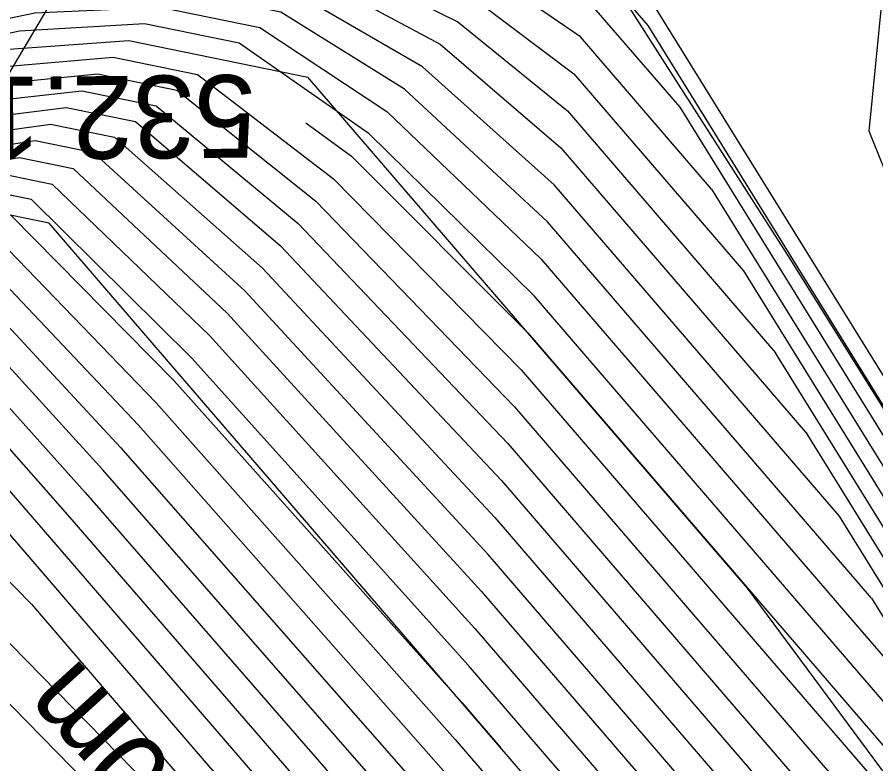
# Model space of a CAD drawing. Extents: x -866683 to -866410, y -1041951 to -1040252.
# Drawn here: x -866456.13 to -866453.011, y -1041913.962 to -1041911.251 of the extents above; entities that cross this region are included whole.
import ezdxf

# ---------------------------------------------------------------- set-up
doc = ezdxf.new("R2010")
doc.units = 0
for name, color, linetype in [('BREAKLINE', 7, 'Continuous'), ('V-HL', 7, 'Continuous'), ('V-VEDL', 7, 'Continuous'), ('V_po_cm', 7, 'Continuous')]:
    doc.layers.add(name, color=color, linetype=linetype)

msp = doc.modelspace()

# ---------------------------------------------------------------- linework, layer by layer
at = {"layer": 'BREAKLINE'}
msp.add_lwpolyline([(-866451.679, -1041950.508), (-866455.618, -1041922.473), (-866456.719, -1041912.396), (-866455.207, -1041909.853), (-866453.752, -1041908.342), (-866450, -1041907.538), (-866447.7, -1041908.076), (-866445.165, -1041909.459), (-866437.422, -1041915.176), (-866426.565, -1041925.108), (-866438.22, -1041915.868), (-866445.312, -1041910.554), (-866447.7, -1041908.076)], dxfattribs=at)
at = {"layer": 'V-HL'}
msp.add_lwpolyline([(-866454.1336, -1041910.9392), (-866453.9375, -1041911.167), (-866453.3211, -1041912.1323), (-866452.4979, -1041913.4504)], dxfattribs=at)
at = {"layer": 'V-VEDL'}
for points in [[(-866464.1795, -1041906.7476), (-866460.1736, -1041910.2204), (-866458.6026, -1041911.3017), (-866457.4635, -1041911.7277), (-866456.7563, -1041911.4985), (-866456.1765, -1041911.3679), (-866455.724, -1041911.3359), (-866455.0738, -1041911.4689)], [(-866456.0139, -1041911.9987), (-866456.2926, -1041911.9417), (-866456.7284, -1041912.0338), (-866457.4606, -1041912.2465), (-866458.4892, -1041912.5798), (-866459.6567, -1041912.3845), (-866460.9629, -1041911.6604), (-866463.8529, -1041909.155)], [(-866437.9513, -1041933.9895), (-866436.2679, -1041931.188), (-866435.7213, -1041930.1825), (-866435.4698, -1041929.5721), (-866435.5134, -1041929.3569), (-866435.5157, -1041928.9796), (-866435.4765, -1041928.44), (-866435.3961, -1041927.7383), (-866436.6575, -1041926.4083), (-866439.2609, -1041924.4499), (-866443.2062, -1041921.8632), (-866446.067, -1041920.1994), (-866447.8432, -1041919.4586), (-866448.5349, -1041919.6407), (-866449.3795, -1041919.1431), (-866450.3771, -1041917.9657), (-866451.5277, -1041916.1086), (-866452.5609, -1041914.5613), (-866453.4767, -1041913.3239), (-866455.0738, -1041911.4689)], [(-866453.6171, -1041916.4043), (-866455.6514, -1041914.0403), (-866456.43, -1041913.2461), (-866456.9701, -1041912.8398), (-866457.2717, -1041912.8213), (-866457.8386, -1041912.9275), (-866458.6706, -1041913.1584), (-866459.7678, -1041913.5139), (-866460.795, -1041913.4946), (-866461.7521, -1041913.1004), (-866463.5263, -1041911.5623)], [(-866439.4444, -1041935.2819), (-866437.4367, -1041931.9407), (-866436.7848, -1041930.7414), (-866436.4848, -1041930.0134), (-866436.5368, -1041929.7567), (-866436.5395, -1041929.3067), (-866436.4928, -1041928.6632), (-866436.3968, -1041927.8263), (-866437.5569, -1041926.4658), (-866439.973, -1041924.5818), (-866443.6451, -1041922.1742), (-866446.3437, -1041920.6351), (-866448.069, -1041919.9646), (-866448.8208, -1041920.1625), (-866449.538, -1041919.9458), (-866450.2207, -1041919.3143), (-866450.8689, -1041918.2681), (-866451.8006, -1041916.9903), (-866453.016, -1041915.4809), (-866456.0139, -1041911.9987)]]:
    msp.add_lwpolyline(points, dxfattribs=at)
at = {"layer": 'V_po_cm'}
for points in [[(-866461.9684, -1041906.7527), (-866459.4633, -1041908.9245), (-866457.654, -1041910.3271), (-866456.5404, -1041910.9608), (-866456.1225, -1041910.8254), (-866455.6798, -1041910.7687), (-866455.2123, -1041910.7907), (-866454.72, -1041910.8914), (-866454.3357, -1041911.0237), (-866454.0595, -1041911.1874), (-866453.7233, -1041911.5779)], [(-866453.0266, -1041913.3603), (-866454.2033, -1041911.9934), (-866454.7225, -1041911.5118), (-866455.1726, -1041911.2321), (-866455.5534, -1041911.1541), (-866456.0109, -1041911.1682), (-866456.5451, -1041911.2741), (-866457.1558, -1041911.4721), (-866458.2864, -1041910.9768), (-866459.9369, -1041909.7884), (-866462.1072, -1041907.9069), (-866463.5789, -1041906.9024)], [(-866453.6072, -1041911.875), (-866454.0835, -1041911.3217), (-866454.4002, -1041911.105), (-866454.7954, -1041910.9482), (-866455.2691, -1041910.8513), (-866455.735, -1041910.8352), (-866456.1929, -1041910.9002), (-866456.643, -1041911.046), (-866457.7594, -1041910.4354), (-866459.5423, -1041909.0685), (-866461.9915, -1041906.9451)], [(-866463.5642, -1041907.1206), (-866462.1303, -1041908.0993), (-866460.0158, -1041909.9324), (-866458.3918, -1041911.0851), (-866457.2584, -1041911.5573), (-866456.6155, -1041911.3489), (-866456.0661, -1041911.2347), (-866455.6103, -1041911.2147), (-866455.248, -1041911.2888), (-866454.787, -1041911.5932), (-866454.2273, -1041912.1278), (-866452.9104, -1041913.6573)], [(-866462.0146, -1041907.1374), (-866459.6212, -1041909.2125), (-866457.8648, -1041910.5437), (-866456.7455, -1041911.1312), (-866456.2634, -1041910.9749), (-866455.7902, -1041910.9018), (-866455.326, -1041910.9118), (-866454.8708, -1041911.005), (-866454.4647, -1041911.1864), (-866454.1075, -1041911.4561), (-866453.4911, -1041912.172)], [(-866452.7943, -1041913.9544), (-866454.2513, -1041912.2621), (-866454.8515, -1041911.6746), (-866455.3234, -1041911.3456), (-866455.6671, -1041911.2753), (-866456.1213, -1041911.3013), (-866456.6859, -1041911.4237), (-866457.361, -1041911.6425), (-866458.4972, -1041911.1934), (-866460.0947, -1041910.0764), (-866462.1534, -1041908.2917), (-866463.5495, -1041907.3388)], [(-866462.0378, -1041907.3298), (-866459.7001, -1041909.3565), (-866457.9702, -1041910.652), (-866456.8481, -1041911.2164), (-866456.3338, -1041911.0497), (-866455.8454, -1041910.9684), (-866455.3829, -1041910.9724), (-866454.9463, -1041911.0617), (-866454.5291, -1041911.2677), (-866454.1314, -1041911.5904), (-866453.3749, -1041912.4691)], [(-866462.0609, -1041907.5222), (-866459.779, -1041909.5005), (-866458.0756, -1041910.7603), (-866456.9507, -1041911.3016), (-866456.4042, -1041911.1245), (-866455.9006, -1041911.035), (-866455.4397, -1041911.033), (-866455.0217, -1041911.1185), (-866454.5936, -1041911.3491), (-866454.1554, -1041911.7247), (-866453.2588, -1041912.7662)], [(-866464.0149, -1041919.5667), (-866464.1225, -1041917.511), (-866464.2372, -1041915.5405), (-866464.3589, -1041913.6552), (-866464.4877, -1041911.8549), (-866464.5437, -1041910.5382), (-866464.5268, -1041909.705), (-866464.4371, -1041909.3554), (-866464.355, -1041908.8981), (-866464.2806, -1041908.3332), (-866464.2137, -1041907.6608), (-866463.5201, -1041907.7752), (-866462.1997, -1041908.6764), (-866460.2526, -1041910.3644), (-866458.708, -1041911.41), (-866457.5661, -1041911.8129), (-866456.8268, -1041911.5733), (-866456.2317, -1041911.4345), (-866455.7809, -1041911.3965), (-866455.4743, -1041911.4592), (-866454.9804, -1041911.8373), (-866454.2992, -1041912.5308), (-866452.5621, -1041914.5485)], [(-866453.1427, -1041913.0632), (-866454.1794, -1041911.8591), (-866454.6581, -1041911.4305), (-866455.0971, -1041911.1753), (-866455.4966, -1041911.0936), (-866455.9557, -1041911.1016), (-866456.4746, -1041911.1993), (-866457.0533, -1041911.3868), (-866458.181, -1041910.8685), (-866459.8579, -1041909.6444), (-866462.084, -1041907.7146)], [(-866463.994, -1041919.6179), (-866464.1029, -1041917.5376), (-866464.2169, -1041915.5731), (-866464.3358, -1041913.7246), (-866464.4598, -1041911.992), (-866464.5119, -1041910.718), (-866464.4922, -1041909.9025), (-866464.4006, -1041909.5456), (-866464.3179, -1041909.0899), (-866464.2441, -1041908.5354), (-866464.1791, -1041907.8823), (-866463.5054, -1041907.9934), (-866462.2228, -1041908.8688), (-866460.3315, -1041910.5084), (-866458.8134, -1041911.5182), (-866457.6687, -1041911.8981), (-866456.8972, -1041911.6481), (-866456.2869, -1041911.5011), (-866455.8377, -1041911.457), (-866455.5498, -1041911.516), (-866455.0449, -1041911.9186), (-866454.3232, -1041912.6651), (-866452.446, -1041914.8455)], [(-866463.9732, -1041919.6692), (-866464.0834, -1041917.5641), (-866464.1965, -1041915.6057), (-866464.3127, -1041913.794), (-866464.4318, -1041912.1292), (-866464.4801, -1041910.8978), (-866464.4575, -1041910.1), (-866464.364, -1041909.7358), (-866464.2807, -1041909.2817), (-866464.2076, -1041908.7376), (-866464.1445, -1041908.1037), (-866463.4907, -1041908.2115), (-866462.2459, -1041909.0611), (-866460.4104, -1041910.6524), (-866458.9188, -1041911.6265), (-866457.7712, -1041911.9833), (-866456.9676, -1041911.7229), (-866456.342, -1041911.5677), (-866455.8946, -1041911.5176), (-866455.6252, -1041911.5727), (-866455.1094, -1041912), (-866454.3471, -1041912.7994), (-866452.3298, -1041915.1426)], [(-866463.9523, -1041919.7205), (-866464.0638, -1041917.5906), (-866464.1762, -1041915.6382), (-866464.2896, -1041913.8635), (-866464.4038, -1041912.2663), (-866464.4483, -1041911.0776), (-866464.4228, -1041910.2975), (-866464.3275, -1041909.926), (-866464.2436, -1041909.4735), (-866464.1711, -1041908.9398), (-866464.11, -1041908.3252), (-866463.476, -1041908.4297), (-866462.2691, -1041909.2535), (-866460.4893, -1041910.7964), (-866459.0242, -1041911.7348), (-866457.8738, -1041912.0686), (-866457.038, -1041911.7977), (-866456.3972, -1041911.6343), (-866455.9514, -1041911.5782), (-866455.7006, -1041911.6295), (-866455.1738, -1041912.0814), (-866454.3711, -1041912.9338), (-866452.2137, -1041915.4397)], [(-866463.9314, -1041919.7718), (-866464.0442, -1041917.6171), (-866464.1559, -1041915.6708), (-866464.2665, -1041913.9329), (-866464.3759, -1041912.4034), (-866464.4164, -1041911.2574), (-866464.3881, -1041910.495), (-866464.291, -1041910.1162), (-866464.2065, -1041909.6652), (-866464.1346, -1041909.142), (-866464.0754, -1041908.5467), (-866463.4613, -1041908.6479), (-866462.2922, -1041909.4459), (-866460.5683, -1041910.9404), (-866459.1296, -1041911.8431), (-866457.9764, -1041912.1538), (-866457.1084, -1041911.8725), (-866456.4524, -1041911.7008), (-866456.0083, -1041911.6388), (-866455.7761, -1041911.6863), (-866455.2383, -1041912.1627), (-866454.3951, -1041913.0681), (-866452.0976, -1041915.7367)], [(-866451.9815, -1041916.0338), (-866454.4191, -1041913.2024), (-866455.3028, -1041912.2441), (-866455.8515, -1041911.7431), (-866456.0651, -1041911.6993), (-866456.5076, -1041911.7674), (-866457.1789, -1041911.9473), (-866458.0789, -1041912.239), (-866459.2351, -1041911.9514), (-866460.6472, -1041911.0844), (-866462.3153, -1041909.6382), (-866463.4466, -1041908.8661), (-866464.0408, -1041908.7681), (-866464.0981, -1041909.3442), (-866464.1693, -1041909.857), (-866464.2544, -1041910.3064), (-866464.3535, -1041910.6925), (-866464.3846, -1041911.4372), (-866464.3479, -1041912.5405), (-866464.2433, -1041914.0023), (-866464.1356, -1041915.7034), (-866464.0247, -1041917.6436), (-866463.9105, -1041919.8231)], [(-866463.8897, -1041919.8744), (-866464.0051, -1041917.6701), (-866464.1153, -1041915.7359), (-866464.2202, -1041914.0717), (-866464.32, -1041912.6776), (-866464.3528, -1041911.617), (-866464.3188, -1041910.89), (-866464.2179, -1041910.4967), (-866464.1322, -1041910.0488), (-866464.0616, -1041909.5464), (-866464.0062, -1041908.9896), (-866463.4319, -1041909.0843), (-866462.3385, -1041909.8306), (-866460.7261, -1041911.2284), (-866459.3405, -1041912.0596), (-866458.1815, -1041912.3242), (-866457.2493, -1041912.0221), (-866456.5628, -1041911.834), (-866456.122, -1041911.7599), (-866455.9269, -1041911.7998), (-866455.3673, -1041912.3255), (-866454.443, -1041913.3368), (-866451.8653, -1041916.3308)], [(-866463.8688, -1041919.9257), (-866463.9855, -1041917.6967), (-866464.0949, -1041915.7685), (-866464.1971, -1041914.1412), (-866464.292, -1041912.8147), (-866464.321, -1041911.7968), (-866464.2841, -1041911.0875), (-866464.1814, -1041910.6869), (-866464.095, -1041910.2406), (-866464.0251, -1041909.7486), (-866463.9717, -1041909.2111), (-866463.4172, -1041909.3025), (-866462.3616, -1041910.023), (-866460.805, -1041911.3724), (-866459.4459, -1041912.1679), (-866458.2841, -1041912.4094), (-866457.3197, -1041912.0969), (-866456.618, -1041911.9006), (-866456.1789, -1041911.8205), (-866456.0024, -1041911.8566), (-866455.4317, -1041912.4068), (-866454.467, -1041913.4711), (-866451.7492, -1041916.6279)], [(-866451.6331, -1041916.9249), (-866454.491, -1041913.6054), (-866455.4962, -1041912.4882), (-866456.0778, -1041911.9134), (-866456.2357, -1041911.8811), (-866456.6732, -1041911.9672), (-866457.3901, -1041912.1717), (-866458.3867, -1041912.4946), (-866459.5513, -1041912.2762), (-866460.884, -1041911.5164), (-866462.3847, -1041910.2153), (-866463.4024, -1041909.5207), (-866463.9371, -1041909.4325), (-866463.9886, -1041909.9508), (-866464.0579, -1041910.4324), (-866464.1448, -1041910.8771), (-866464.2495, -1041911.285), (-866464.2892, -1041911.9766), (-866464.264, -1041912.9518), (-866464.174, -1041914.2106), (-866464.0746, -1041915.8011), (-866463.9659, -1041917.7232), (-866463.8479, -1041919.9769)], [(-866448.1918, -1041919.0146), (-866449.1759, -1041918.2014), (-866450.5246, -1041916.4121), (-866452.238, -1041913.6466), (-866453.0351, -1041911.6643), (-866452.916, -1041910.4653), (-866451.8807, -1041910.0496), (-866451.1969, -1041909.7645), (-866450.8647, -1041909.6101), (-866450.8839, -1041909.5864), (-866450.889, -1041909.5577), (-866450.8798, -1041909.524), (-866450.8563, -1041909.4853), (-866450.853, -1041909.4547), (-866450.8698, -1041909.4323), (-866450.9438, -1041909.4039)], [(-866463.8062, -1041920.0795), (-866463.9268, -1041917.7762), (-866464.034, -1041915.8662), (-866464.1278, -1041914.3495), (-866464.2081, -1041913.226), (-866464.2256, -1041912.3362), (-866464.1801, -1041911.68), (-866464.0717, -1041911.2575), (-866463.9836, -1041910.8159), (-866463.9156, -1041910.3552), (-866463.8679, -1041909.8755), (-866463.373, -1041909.9571), (-866462.431, -1041910.6001), (-866461.0418, -1041911.8044), (-866459.7621, -1041912.4928), (-866458.5918, -1041912.665), (-866457.531, -1041912.3213), (-866456.7835, -1041912.1004), (-866456.3494, -1041912.0022), (-866456.2287, -1041912.0269), (-866455.6252, -1041912.6509), (-866454.5389, -1041913.8741), (-866451.4009, -1041917.519)], [(-866463.7853, -1041920.1308), (-866463.9072, -1041917.8027), (-866464.0137, -1041915.8988), (-866464.1046, -1041914.4189), (-866464.1802, -1041913.3631), (-866464.1938, -1041912.516), (-866464.1455, -1041911.8775), (-866464.0352, -1041911.4477), (-866463.9464, -1041911.0077), (-866463.8791, -1041910.5574), (-866463.8334, -1041910.0969), (-866463.3583, -1041910.1753), (-866462.4541, -1041910.7924), (-866461.1207, -1041911.9484), (-866459.8675, -1041912.601), (-866458.6944, -1041912.7503), (-866457.6014, -1041912.3961), (-866456.8387, -1041912.1669), (-866456.4063, -1041912.0628), (-866456.3041, -1041912.0837), (-866455.6896, -1041912.7323), (-866454.5629, -1041914.0085), (-866451.2847, -1041917.8161)], [(-866463.7645, -1041920.1821), (-866463.8876, -1041917.8293), (-866463.9933, -1041915.9313), (-866464.0815, -1041914.4883), (-866464.1522, -1041913.5002), (-866464.162, -1041912.6958), (-866464.1108, -1041912.075), (-866463.9987, -1041911.638), (-866463.9093, -1041911.1995), (-866463.8427, -1041910.7596), (-866463.7988, -1041910.3184), (-866463.3436, -1041910.3934), (-866462.4773, -1041910.9848), (-866461.1996, -1041912.0924), (-866459.9729, -1041912.7093), (-866458.7969, -1041912.8355), (-866457.6718, -1041912.4709), (-866456.8939, -1041912.2335), (-866456.4631, -1041912.1234), (-866456.3795, -1041912.1405), (-866455.7541, -1041912.8136), (-866454.5868, -1041914.1428), (-866451.1686, -1041918.1132)], [(-866451.0525, -1041918.4102), (-866454.6108, -1041914.2771), (-866455.8186, -1041912.895), (-866456.455, -1041912.1973), (-866456.52, -1041912.184), (-866456.9491, -1041912.3001), (-866457.7423, -1041912.5457), (-866458.8995, -1041912.9207), (-866460.0783, -1041912.8176), (-866461.2786, -1041912.2364), (-866462.5004, -1041911.1772), (-866463.3289, -1041910.6116), (-866463.7642, -1041910.5399), (-866463.8062, -1041910.9618), (-866463.8721, -1041911.3913), (-866463.9621, -1041911.8282), (-866464.0761, -1041912.2725), (-866464.1302, -1041912.8756), (-866464.1243, -1041913.6373), (-866464.0584, -1041914.5578), (-866463.973, -1041915.9639), (-866463.8681, -1041917.8558), (-866463.7436, -1041920.2334)], [(-866455.5596, -1041910.706), (-866455.1554, -1041910.7301), (-866454.6445, -1041910.8346), (-866454.2712, -1041910.9423), (-866454.0356, -1041911.0531), (-866453.8394, -1041911.2809)], [(-866463.7227, -1041920.2847), (-866463.8485, -1041917.8823), (-866463.9527, -1041915.9965), (-866464.0353, -1041914.6272), (-866464.0963, -1041913.7744), (-866464.0983, -1041913.0554), (-866464.0414, -1041912.47), (-866463.9256, -1041912.0184), (-866463.835, -1041911.5831), (-866463.7697, -1041911.164), (-866463.7296, -1041910.7613), (-866463.3142, -1041910.8298), (-866462.5235, -1041911.3695), (-866461.3575, -1041912.3804), (-866460.1837, -1041912.9259), (-866459.0021, -1041913.0059), (-866457.8127, -1041912.6205), (-866457.0043, -1041912.3667), (-866456.5769, -1041912.2446), (-866456.5304, -1041912.2541), (-866455.883, -1041912.9764), (-866454.6348, -1041914.4115), (-866450.9364, -1041918.7073)], [(-866463.7019, -1041920.3359), (-866463.8289, -1041917.9088), (-866463.9324, -1041916.029), (-866464.0122, -1041914.6966), (-866464.0683, -1041913.9116), (-866464.0665, -1041913.2352), (-866464.0068, -1041912.6675), (-866463.889, -1041912.2086), (-866463.7978, -1041911.7748), (-866463.7332, -1041911.3662), (-866463.695, -1041910.9828), (-866463.2995, -1041911.048), (-866462.5467, -1041911.5619), (-866461.4364, -1041912.5244), (-866460.2891, -1041913.0342), (-866459.1046, -1041913.0911), (-866457.8831, -1041912.6953), (-866457.0595, -1041912.4333), (-866456.6337, -1041912.3051), (-866456.6058, -1041912.3108), (-866455.9475, -1041913.0577), (-866454.6587, -1041914.5458), (-866450.8202, -1041919.0043)], [(-866453.9556, -1041910.9838), (-866450.5491, -1041916.4822), (-866449.2051, -1041918.2601), (-866448.2204, -1041919.0667), (-866447.5949, -1041918.902), (-866445.7626, -1041919.7202), (-866442.7235, -1041921.5211), (-866438.4776, -1041924.3049), (-866435.6682, -1041926.3451), (-866434.2952, -1041927.6416), (-866434.3586, -1041928.1946), (-866434.3894, -1041928.6198), (-866434.3877, -1041928.9172), (-866434.3533, -1041929.0867), (-866434.5515, -1041929.5677), (-866434.9823, -1041930.3602), (-866436.3089, -1041932.5679)], [(-866463.681, -1041920.3872), (-866463.8094, -1041917.9353), (-866463.912, -1041916.0616), (-866463.989, -1041914.766), (-866464.0404, -1041914.0487), (-866464.0347, -1041913.415), (-866463.9721, -1041912.865), (-866463.8525, -1041912.3988), (-866463.7607, -1041911.9666), (-866463.6967, -1041911.5684), (-866463.6605, -1041911.2043), (-866463.2848, -1041911.2662), (-866462.5698, -1041911.7543), (-866461.5153, -1041912.6684), (-866460.3945, -1041913.1424), (-866459.2072, -1041913.1763), (-866457.9535, -1041912.7701), (-866457.1147, -1041912.4999), (-866456.6906, -1041912.3657), (-866456.6813, -1041912.3676), (-866456.012, -1041913.1391), (-866454.6827, -1041914.6801), (-866450.7041, -1041919.3014)], [(-866453.8394, -1041911.2809), (-866452.7335, -1041913.066)], [(-866453.7233, -1041911.5779), (-866450.5178, -1041916.7519), (-866449.2368, -1041918.4207), (-866448.2776, -1041919.1711), (-866447.64, -1041919.0032), (-866445.8179, -1041919.8073), (-866442.8113, -1041921.5833), (-866438.6201, -1041924.3313), (-866435.8481, -1041926.3566), (-866434.4954, -1041927.6592), (-866434.5619, -1041928.2392), (-866434.5942, -1041928.6852), (-866434.5924, -1041928.9971), (-866434.5563, -1041929.175), (-866434.7642, -1041929.6795), (-866435.216, -1041930.5107), (-866436.6075, -1041932.8263)], [(-866455.0814, -1041911.6348), (-866454.916, -1041911.7559), (-866454.2752, -1041912.3964), (-866452.6782, -1041914.2514)], [(-866453.6072, -1041911.875), (-866450.5022, -1041916.8868), (-866449.2527, -1041918.5009), (-866448.3062, -1041919.2233), (-866447.6626, -1041919.0538), (-866445.8456, -1041919.8509), (-866442.8552, -1041921.6144), (-866438.6913, -1041924.3444), (-866435.938, -1041926.3623), (-866434.5954, -1041927.668), (-866434.6635, -1041928.2615), (-866434.6966, -1041928.7179), (-866434.6947, -1041929.0371), (-866434.6578, -1041929.2191), (-866434.8706, -1041929.7354), (-866435.3329, -1041930.586), (-866436.7568, -1041932.9556)], [(-866457.6353, -1041912.3031), (-866457.4606, -1041912.2465), (-866456.7284, -1041912.0338), (-866456.2926, -1041911.9417), (-866456.1532, -1041911.9702), (-866455.5607, -1041912.5695), (-866454.5149, -1041913.7398), (-866454.3758, -1041913.9013)], [(-866453.4911, -1041912.172), (-866450.4866, -1041917.0217), (-866449.2685, -1041918.5812), (-866448.3348, -1041919.2755), (-866447.6852, -1041919.1044), (-866445.8733, -1041919.8945), (-866442.899, -1041921.6455), (-866438.7625, -1041924.3576), (-866436.028, -1041926.3681), (-866434.6955, -1041927.6768), (-866434.7651, -1041928.2839), (-866434.799, -1041928.7506), (-866434.797, -1041929.0771), (-866434.7593, -1041929.2632), (-866434.9769, -1041929.7913), (-866435.4498, -1041930.6612), (-866436.9061, -1041933.0848)], [(-866450.588, -1041919.5984), (-866454.2618, -1041915.3313), (-866455.5541, -1041913.8301), (-866456.3021, -1041912.9613), (-866456.5055, -1041912.7249), (-866456.6612, -1041912.566), (-866456.7692, -1041912.4848), (-866456.8295, -1041912.4811), (-866457.2815, -1041912.612), (-866458.1251, -1041912.8776), (-866459.3604, -1041913.2779), (-866460.5167, -1041913.2562)], [(-866437.0554, -1041933.2141), (-866435.5667, -1041930.7365), (-866435.0833, -1041929.8472), (-866434.8608, -1041929.3074), (-866434.8994, -1041929.1171), (-866434.9014, -1041928.7833), (-866434.8668, -1041928.3062), (-866434.7956, -1041927.6856), (-866436.1179, -1041926.3738), (-866438.8337, -1041924.3708), (-866442.9429, -1041921.6766), (-866445.901, -1041919.938), (-866447.7078, -1041919.155), (-866448.3633, -1041919.3276), (-866449.2844, -1041918.6615), (-866450.4709, -1041917.1565), (-866453.3749, -1041912.4691)], [(-866460.6559, -1041913.3754), (-866459.5641, -1041913.3959), (-866458.3978, -1041913.018), (-866457.56, -1041912.7697), (-866457.0506, -1041912.6512), (-866456.8697, -1041912.6623), (-866456.5456, -1041912.9061), (-866456.0784, -1041913.3826), (-866455.4682, -1041914.0918), (-866454.574, -1041915.1306), (-866453.3959, -1041916.4992), (-866450.4719, -1041919.8955)], [(-866437.2047, -1041933.3433), (-866435.6835, -1041930.8117), (-866435.1896, -1041929.9031), (-866434.9623, -1041929.3515), (-866435.0017, -1041929.157), (-866435.0037, -1041928.816), (-866434.9684, -1041928.3285), (-866434.8957, -1041927.6944), (-866436.2078, -1041926.3796), (-866438.9049, -1041924.384), (-866442.9868, -1041921.7077), (-866445.9286, -1041919.9816), (-866447.7303, -1041919.2056), (-866448.3919, -1041919.3798), (-866449.3002, -1041918.7417), (-866450.4553, -1041917.2914), (-866453.2588, -1041912.7662)], [(-866451.6641, -1041918.835), (-866452.6136, -1041917.7318), (-866453.8004, -1041916.3528), (-866455.2243, -1041914.698), (-866456.3144, -1041913.5861), (-866457.0706, -1041913.0173), (-866457.4928, -1041912.9914), (-866458.1171, -1041913.0852), (-866458.9433, -1041913.2987), (-866459.9715, -1041913.6319)], [(-866437.354, -1041933.4725), (-866435.8004, -1041930.887), (-866435.296, -1041929.959), (-866435.0638, -1041929.3956), (-866435.1041, -1041929.197), (-866435.1061, -1041928.8487), (-866435.07, -1041928.3508), (-866434.9958, -1041927.7032), (-866436.2978, -1041926.3853), (-866438.9761, -1041924.3972), (-866443.0307, -1041921.7388), (-866445.9563, -1041920.0252), (-866447.7529, -1041919.2562), (-866448.4205, -1041919.432), (-866449.3161, -1041918.822), (-866450.4397, -1041917.4262), (-866453.1427, -1041913.0632)], [(-866453.0266, -1041913.3603), (-866450.424, -1041917.5611), (-866449.332, -1041918.9023), (-866448.4491, -1041919.4842), (-866447.7755, -1041919.3068), (-866445.984, -1041920.0687), (-866443.0746, -1041921.7699), (-866439.0473, -1041924.4104), (-866436.3877, -1041926.3911), (-866435.0958, -1041927.712), (-866435.1717, -1041928.3731), (-866435.2085, -1041928.8815), (-866435.2064, -1041929.237), (-866435.1653, -1041929.4398), (-866435.4023, -1041930.0148), (-866435.9173, -1041930.9623), (-866437.5033, -1041933.6018)]]:
    msp.add_lwpolyline(points, dxfattribs=at)

# ---------------------------------------------------------------- texts
for s, rotation, p in [('532.10m', 180.4477, (-866455.2638, -1041911.4604)), ('532.30m', 132.3671, (-866454.8708, -1041914.7235))]:
    msp.add_text(s, height=0.3, rotation=rotation, dxfattribs=at).set_placement(p)

doc.saveas('drawing.dxf')
